(* Logix 5000 project; controller Soda_Ash vendor 1 type 14 code 92 rev 35.11; software revision 35.00; part 3 of 3 *)
(* tags used below, declared in another part *)
   C6100 : Motor_Conv_Type;   // C-6100 Soda Ash Screw Conveyor
   C6100_Aux : BOOL;   // C-6100 Soda Ash Screw Conveyor Aux. Contact
   C6100_FailESdwn_Tmr : TIMER;   // C-6100 Soda Ash Screw Conveyor Fail to Eshutfown Timer
   G6000 : Gate_Slide_Type;   // G-6000 CIP Tank Slide Gate
   G6000_FailESdwn_Tmr : TIMER;   // G-6000 CIP Tank Slide Gate Fail to Eshutdown Timer
   L6100 : Motor_Std_Type;   // L-6100 Soda Ash Airlock
   L6100_FailSdwn_Tmr : TIMER;   // L-6100 Soda Ash Airlock Fail to Shutdown Timer
   L6100_Level_Alarm_Tmr : TIMER;   // L-6100 Low Bin Indicator Alarm Timer
   L6100_Level_Sdwn_Tmr : TIMER;   // L6100 low level when Transfer Running Shutdown Timer
   LSL6100 : BOOL;   // B-6000 Soda Ash Tank Low Level Switch
   LSL6100_Alarm : BOOL;   // Soda Ash L-6100 Low Bin Indicator Alarm
   Soda_Ash : Unit_Type;   // Soda Ash Unit
   Soda_Ash_EShutdown : Seq_Type;   // Soda Ash E-Shutdown
   Soda_Ash_EShutdown_Tmr : TIMER;   // Soda Ash B-6000 E-Shutdown In Progress Timer
   Soda_Ash_Hold : Seq_Type;   // Soda Ash Hold
   Soda_Ash_Shutdown : Seq_Type;   // Soda Ash Shutdown
   Soda_Ash_StrtTrans : Seq_Type;   // Soda Ash Start Transfer
   SS6100 : BOOL;   // C-6100 Soda Ash Screw Conveyor Zero Speed Switch
   SS6100_Alarm : BOOL;   // SS6100 Speed switch off when running alarm
   SS6100_Fail_Tmr : TIMER;   // SS6100 Soda Ash Screw Conveyor Failure Timer
   SS6100_Off_ESdwn_Tmr : TIMER;   // SS6100 off when Transfer Running EShutdown Timer
   XV1001 : Valve_Disc_Type;   // XV1001 Soda Ash Outlet Valve
   XV1001_CloseLS : BOOL;   // XV1001 Soda Ash Outlet Valve Closed Limit Switch
   XV1001_DB : Valve_Disc;   // XV1001 Soda Ash Outlet Valve
   XV1001_OpenLS : BOOL;   // XV1001 Soda Ash Outlet Valve Open Limit Switch
   XV1001_Sol_Vlv : BOOL;   // XV1001 Soda Ash Outlet Valve Solenoid
(* Soda_Ash, continued *)

ROUTINE Soda_Ash_060EShutdown   (* ladder *)
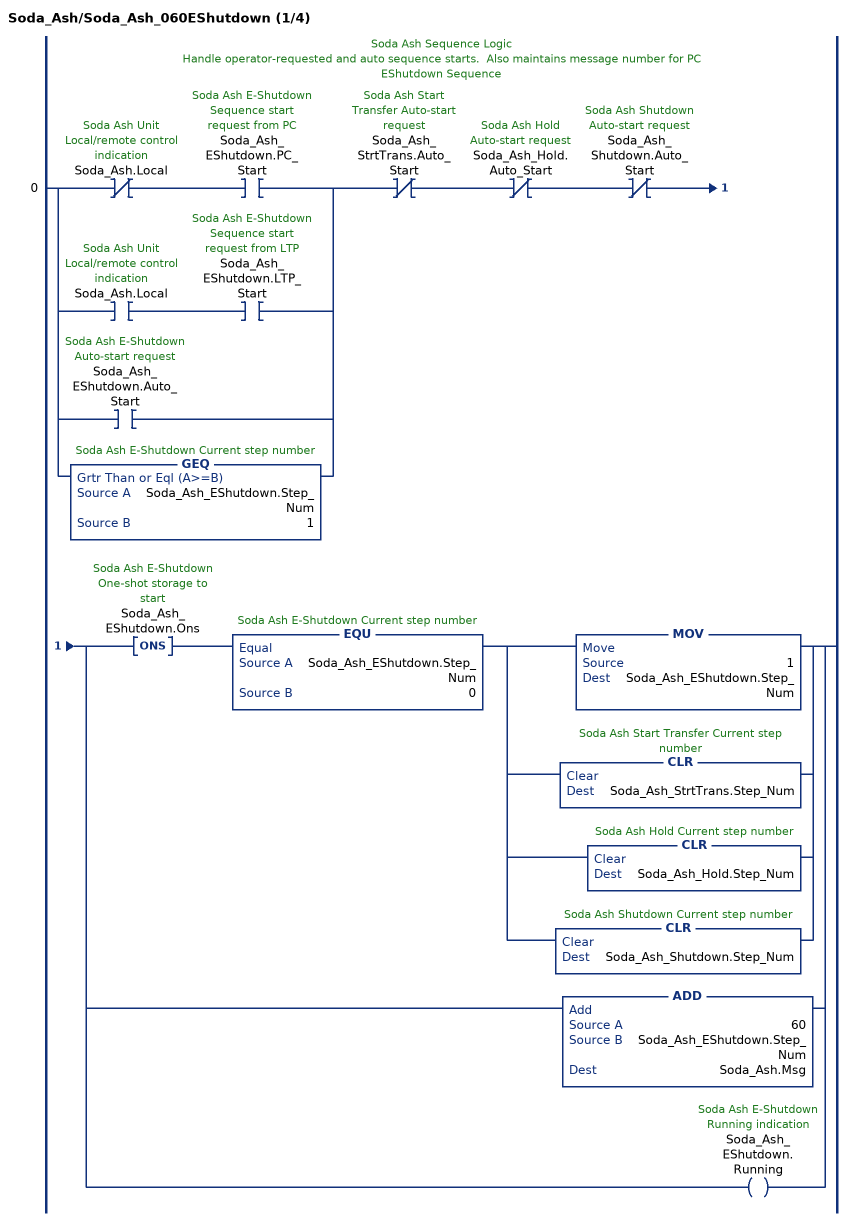
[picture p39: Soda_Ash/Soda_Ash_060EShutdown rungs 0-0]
   // Soda Ash Sequence Logic
   // Handle operator-requested and auto sequence starts.  Also maintains message number for PC
   // EShutdown Sequence
   0: [XIO(Soda_Ash.Local) XIC(Soda_Ash_EShutdown.PC_Start) ,XIC(Soda_Ash.Local) XIC(Soda_Ash_EShutdown.LTP_Start) ,XIC(Soda_Ash_EShutdown.Auto_Start) ,GEQ(Soda_Ash_EShutdown.Step_Num,1) ]XIO(Soda_Ash_StrtTrans.Auto_Start)XIO(Soda_Ash_Hold.Auto_Start)XIO(Soda_Ash_Shutdown.Auto_Start)[ONS(Soda_Ash_EShutdown.Ons) EQU(Soda_Ash_EShutdown.Step_Num,0) [MOV(1,Soda_Ash_EShutdown.Step_Num) ,CLR(Soda_Ash_StrtTrans.Step_Num) ,CLR(Soda_Ash_Hold.Step_Num) ,CLR(Soda_Ash_Shutdown.Step_Num) ] ,ADD(60,Soda_Ash_EShutdown.Step_Num,Soda_Ash.Msg) ,OTE(Soda_Ash_EShutdown.Running) ];
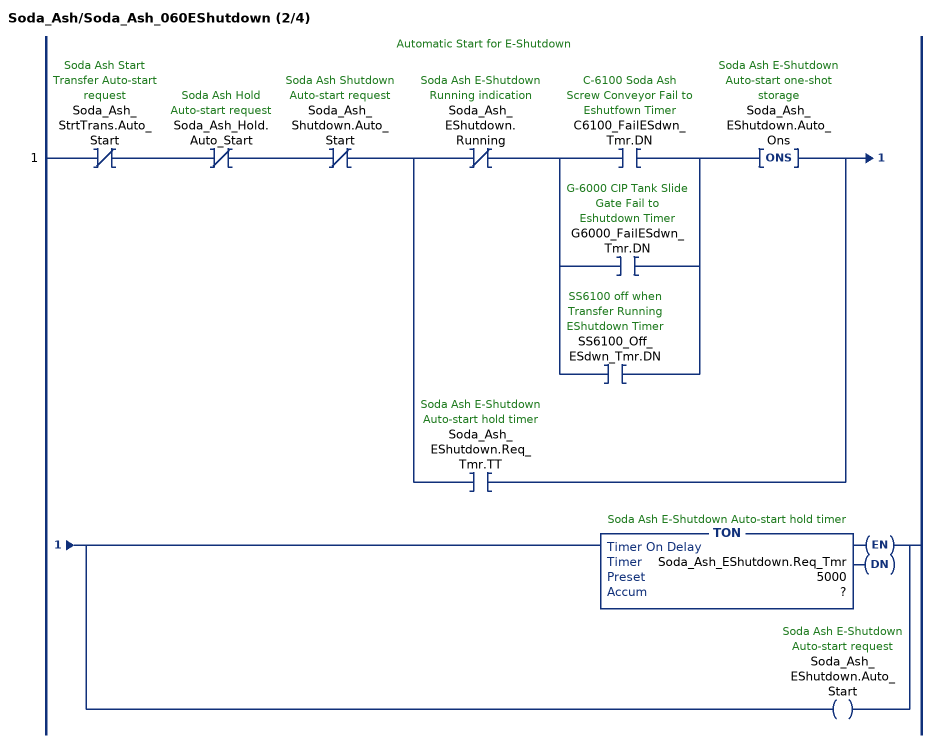
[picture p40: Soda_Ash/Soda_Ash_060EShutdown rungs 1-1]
   // Automatic Start for E-Shutdown
   1: XIO(Soda_Ash_StrtTrans.Auto_Start)XIO(Soda_Ash_Hold.Auto_Start)XIO(Soda_Ash_Shutdown.Auto_Start)[XIO(Soda_Ash_EShutdown.Running) [XIC(C6100_FailESdwn_Tmr.DN) ,XIC(G6000_FailESdwn_Tmr.DN) ,XIC(SS6100_Off_ESdwn_Tmr.DN) ] ONS(Soda_Ash_EShutdown.Auto_Ons) ,XIC(Soda_Ash_EShutdown.Req_Tmr.TT) ][TON(Soda_Ash_EShutdown.Req_Tmr,?,?) ,OTE(Soda_Ash_EShutdown.Auto_Start) ];
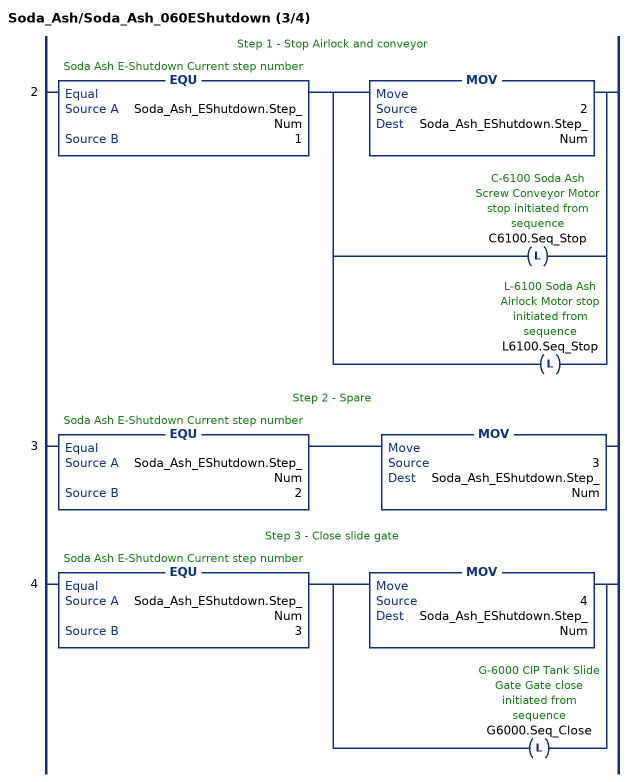
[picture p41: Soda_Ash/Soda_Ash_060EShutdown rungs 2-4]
   // Step 1 - Stop Airlock and conveyor
   2: EQU(Soda_Ash_EShutdown.Step_Num,1)[MOV(2,Soda_Ash_EShutdown.Step_Num) ,OTL(C6100.Seq_Stop) ,OTL(L6100.Seq_Stop) ];
   // Step 2 - Spare
   3: EQU(Soda_Ash_EShutdown.Step_Num,2)MOV(3,Soda_Ash_EShutdown.Step_Num);
   // Step 3 - Close slide gate
   4: EQU(Soda_Ash_EShutdown.Step_Num,3)[MOV(4,Soda_Ash_EShutdown.Step_Num) ,OTL(G6000.Seq_Close) ];
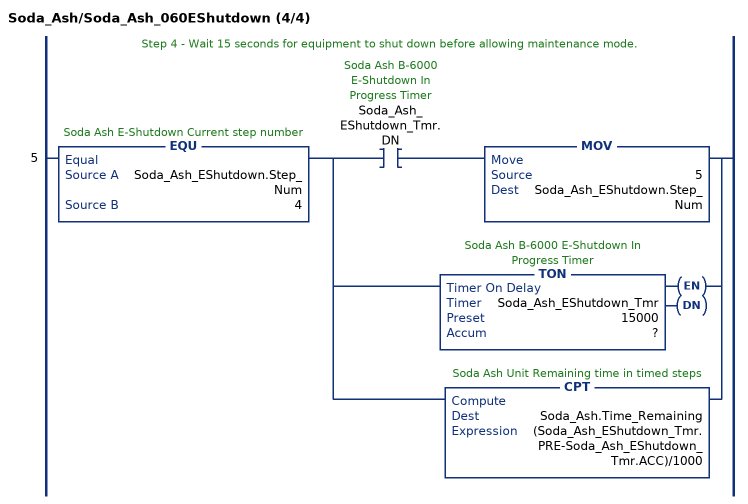
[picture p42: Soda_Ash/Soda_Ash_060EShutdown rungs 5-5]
   // Step 4 - Wait 15 seconds for equipment to shut down before allowing maintenance mode.
   5: EQU(Soda_Ash_EShutdown.Step_Num,4)[XIC(Soda_Ash_EShutdown_Tmr.DN) MOV(5,Soda_Ash_EShutdown.Step_Num) ,TON(Soda_Ash_EShutdown_Tmr,?,?) ,CPT(Soda_Ash.Time_Remaining,(Soda_Ash_EShutdown_Tmr.PRE-Soda_Ash_EShutdown_Tmr.ACC)/1000) ];
END_ROUTINE

ROUTINE Soda_Ash_Abnormal   (* ladder *)
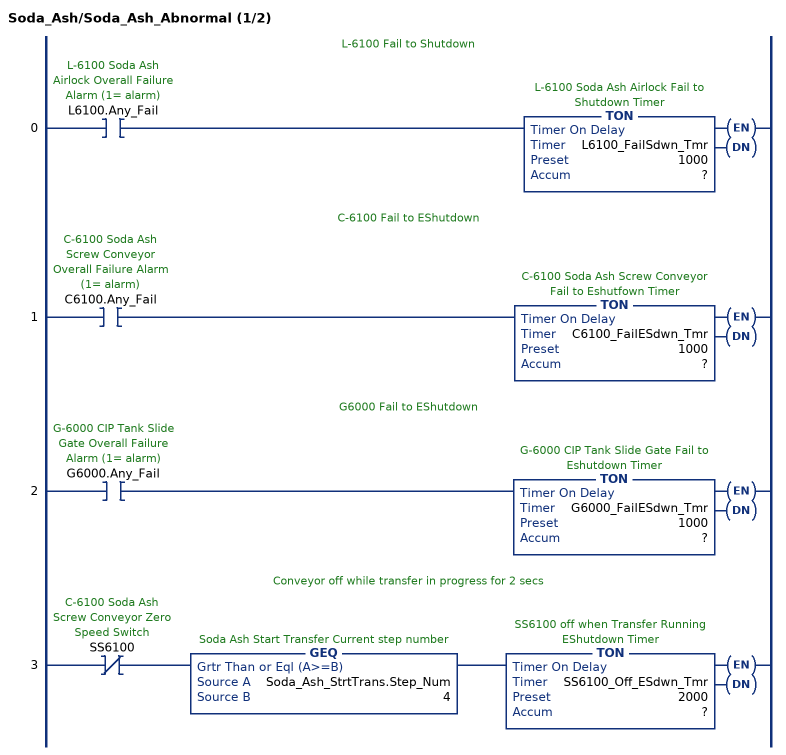
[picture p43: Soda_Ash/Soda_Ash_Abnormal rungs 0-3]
   // L-6100 Fail to Shutdown
   0: XIC(L6100.Any_Fail)TON(L6100_FailSdwn_Tmr,?,?);
   // C-6100 Fail to EShutdown
   1: XIC(C6100.Any_Fail)TON(C6100_FailESdwn_Tmr,?,?);
   // G6000 Fail to EShutdown
   2: XIC(G6000.Any_Fail)TON(G6000_FailESdwn_Tmr,?,?);
   // Conveyor off while transfer in progress for 2 secs
   3: XIO(SS6100)GEQ(Soda_Ash_StrtTrans.Step_Num,4)TON(SS6100_Off_ESdwn_Tmr,?,?);
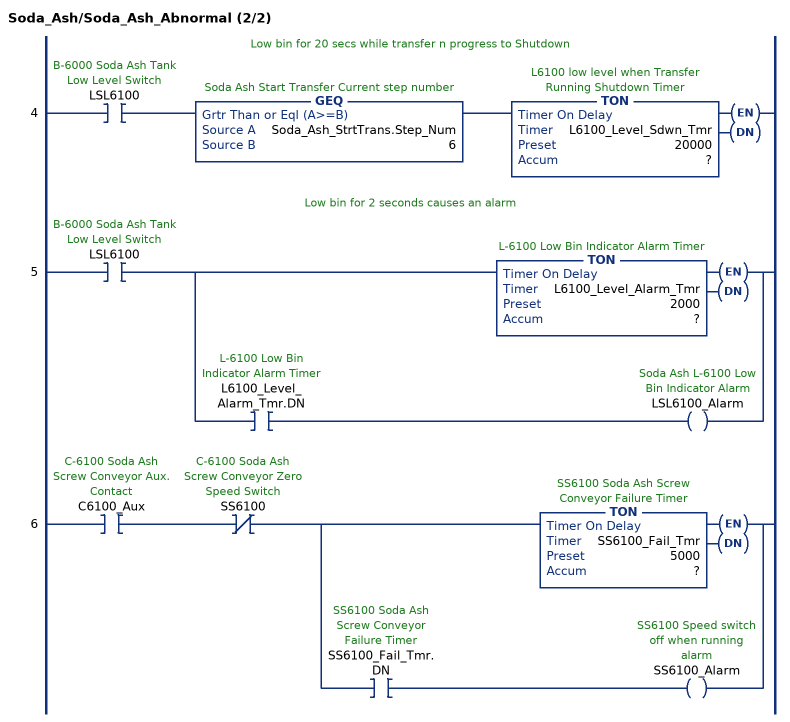
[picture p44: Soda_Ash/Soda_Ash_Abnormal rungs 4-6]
   // Low bin for 20 secs while transfer n progress to Shutdown
   4: XIC(LSL6100)GEQ(Soda_Ash_StrtTrans.Step_Num,6)TON(L6100_Level_Sdwn_Tmr,?,?);
   // Low bin for 2 seconds causes an alarm
   5: XIC(LSL6100)[TON(L6100_Level_Alarm_Tmr,?,?) ,XIC(L6100_Level_Alarm_Tmr.DN) OTE(LSL6100_Alarm) ];
   6: XIC(C6100_Aux)XIO(SS6100)[TON(SS6100_Fail_Tmr,?,?) ,XIC(SS6100_Fail_Tmr.DN) OTE(SS6100_Alarm) ];
END_ROUTINE

ROUTINE Soda_Ash_Misc   (* ladder *)
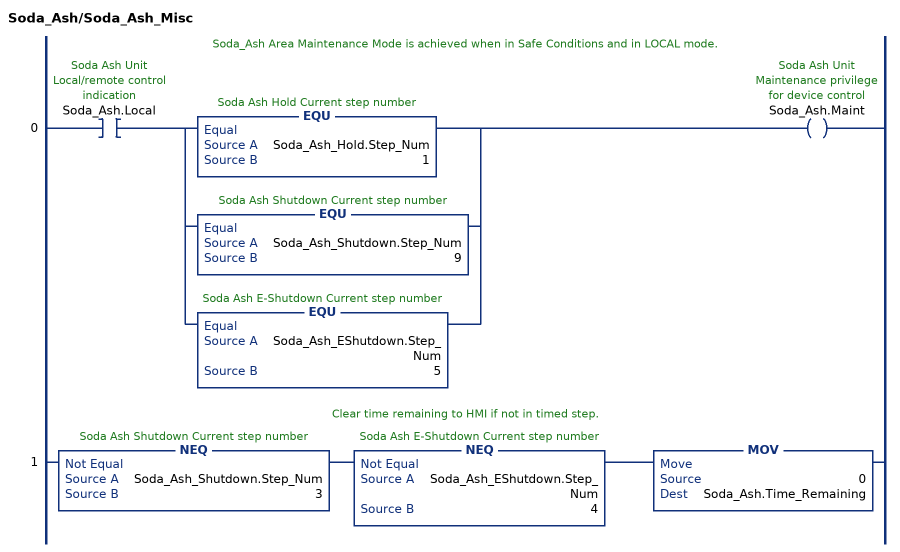
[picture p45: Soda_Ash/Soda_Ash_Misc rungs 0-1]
   // Soda_Ash Area Maintenance Mode is achieved when in Safe Conditions and in LOCAL mode.
   0: XIC(Soda_Ash.Local)[EQU(Soda_Ash_Hold.Step_Num,1) ,EQU(Soda_Ash_Shutdown.Step_Num,9) ,EQU(Soda_Ash_EShutdown.Step_Num,5) ]OTE(Soda_Ash.Maint);
   // Clear time remaining to HMI if not in timed step.
   1: NEQ(Soda_Ash_Shutdown.Step_Num,3)NEQ(Soda_Ash_EShutdown.Step_Num,4)MOV(0,Soda_Ash.Time_Remaining);
END_ROUTINE

ROUTINE Valves   (* ladder *)
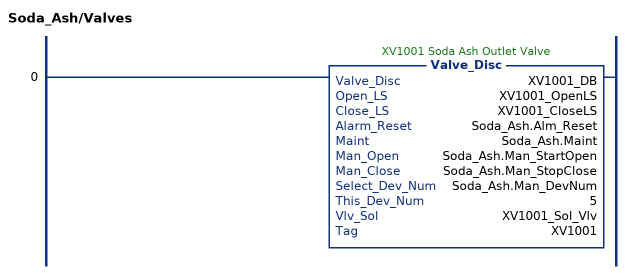
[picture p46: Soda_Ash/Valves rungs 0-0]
   0: Valve_Disc(XV1001_DB,XV1001_OpenLS,XV1001_CloseLS,Soda_Ash.Alm_Reset,Soda_Ash.Maint,Soda_Ash.Man_StartOpen,Soda_Ash.Man_StopClose,Soda_Ash.Man_DevNum,5,XV1001_Sol_Vlv,XV1001);
END_ROUTINE
END_PROGRAM
